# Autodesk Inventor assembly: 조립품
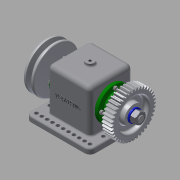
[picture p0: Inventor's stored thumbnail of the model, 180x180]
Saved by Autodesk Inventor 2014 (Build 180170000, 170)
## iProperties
Created: 2018-11
Part Number: 조립품
Document SubType Name: Assembly
Designer: kh
Author: kh
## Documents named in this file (13)
- C:\Users\kh\Desktop\481107V1023\조립품.iam
- C:\Users\kh\Desktop\481107V1023\본체.ipt
- C:\Users\kh\Desktop\481107V1023\V벨트풀리.ipt
- C:\Users\kh\Desktop\481107V1023\너트 M12x1.25.ipt
- C:\Users\kh\Desktop\481107V1023\베어링 6203.ipt
- C:\Users\kh\Desktop\481107V1023\볼트 M4.ipt
- C:\Users\kh\Desktop\481107V1023\부시.ipt
- C:\Users\kh\Desktop\481107V1023\스퍼기어.ipt
- C:\Users\kh\Desktop\481107V1023\오일 실 26 38 8.ipt
- C:\Users\kh\Desktop\481107V1023\와셔 12x24.ipt
- C:\Users\kh\Desktop\481107V1023\축.ipt
- C:\Users\kh\Desktop\481107V1023\커버.ipt
- C:\Users\kh\Desktop\481107V1023\키 5x5x12.ipt
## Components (1 placed, 1 different names)
1. V벨트풀리:1
